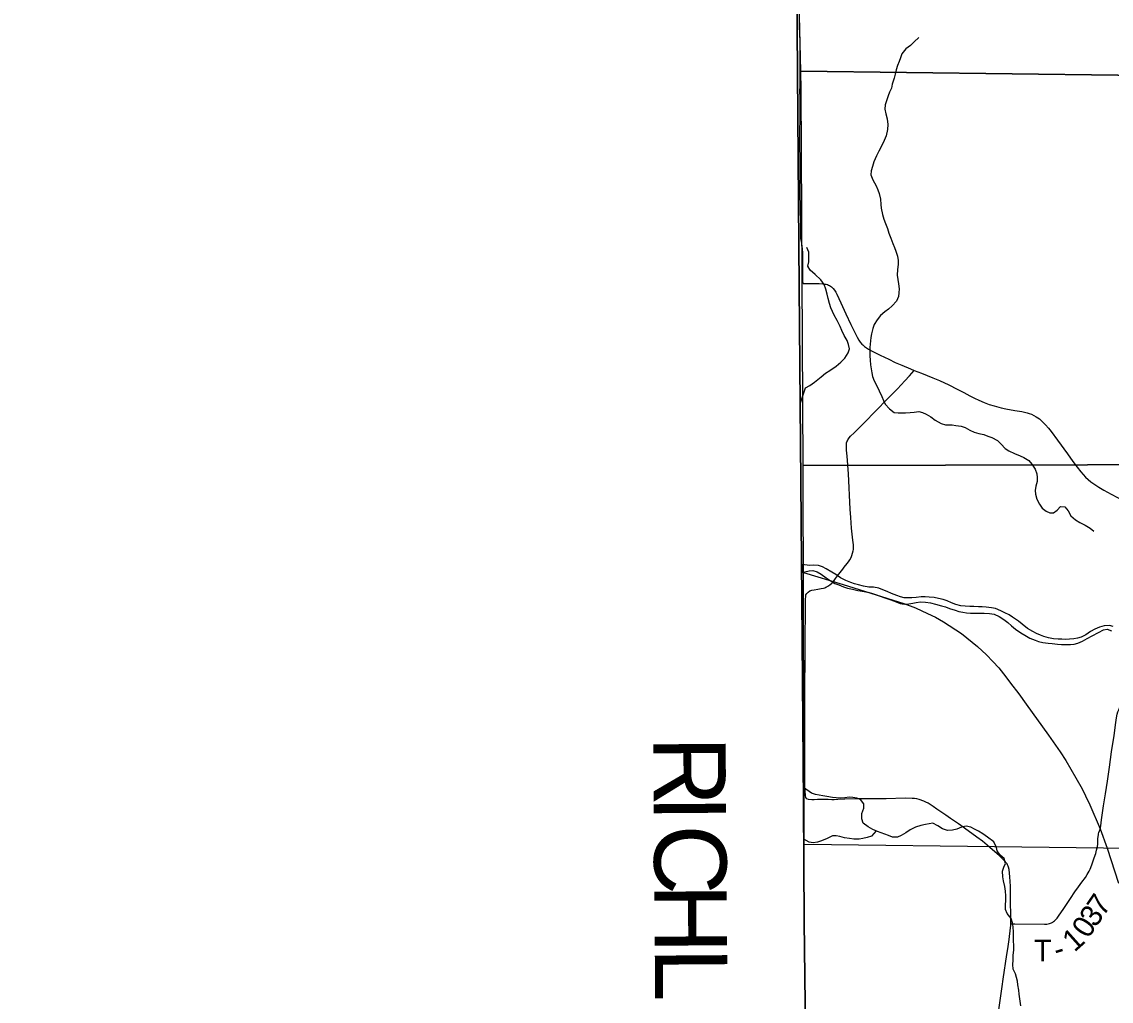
# Model space of a CAD drawing. Extents: x 1874609 to 2204689, y 815661 to 1281160.
# Drawn here: x 2002342 to 2017400, y 975217 to 988761 of the extents above; entities that cross this region are included whole.
import ezdxf

# ---------------------------------------------------------------- set-up
doc = ezdxf.new("R2010")
doc.units = 0
for name, color, linetype in [('GM_X_Adjacent_County', 7, 'Continuous'), ('GM_X_Adjacent_County_Text', 7, 'Continuous'), ('GM_X_County', 7, 'Continuous'), ('GM_X_County_Road', 7, 'Continuous'), ('GM_X_Major_River', 7, 'Continuous'), ('GM_X_Minor_River', 7, 'Continuous'), ('GM_X_Rail_Line', 7, 'Continuous'), ('GM_X_Section', 7, 'Continuous'), ('GM_X_State_Route', 7, 'Continuous'), ('GM_X_Township', 7, 'Continuous'), ('GM_X_Township_Road', 7, 'Continuous'), ('GM_X_Township_Road_Text', 7, 'Continuous')]:
    doc.layers.add(name, color=color, linetype=linetype)

msp = doc.modelspace()

# ---------------------------------------------------------------- linework, layer by layer
at = {"layer": 'GM_X_Adjacent_County'}
msp.add_lwpolyline([(2002342, 999536), (2002395, 993238), (2002881, 993241), (2003206, 993234), (2004504, 993233), (2007698, 993231), (2008414, 993238), (2008503, 993236), (2013055, 993227), (2013045, 990449), (2013083, 985682), (2013088, 985095), (2013122, 980772), (2013145, 977956), (2013158, 976319), (2013226, 970636), (2013231, 969069), (2013234, 968580), (2013273, 965999), (2013327, 961098), (2013338, 960130), (2013382, 956206), (2013389, 955699), (2013479, 950530)], dxfattribs=at)
at = {"layer": 'GM_X_County'}
msp.add_lwpolyline([(2013479, 950530), (2013389, 955699), (2013382, 956206), (2013338, 960130), (2013327, 961098), (2013273, 965999), (2013234, 968580), (2013231, 969069), (2013226, 970636), (2013158, 976319), (2013145, 977956), (2013122, 980772), (2013088, 985095), (2013083, 985682), (2013045, 990449), (2013055, 993227), (2008503, 993236), (2008414, 993238), (2007698, 993231), (2004504, 993233), (2003206, 993234), (2002881, 993241), (2002395, 993238), (2002342, 999536)], dxfattribs=at)
at = {"layer": 'GM_X_County_Road'}
for points in [[(2013711, 981218), (2013751, 981268), (2013770, 981295), (2013788, 981323), (2013804, 981352), (2013816, 981383), (2013826, 981415), (2013834, 981447), (2013836, 981464), (2013838, 981497), (2013836, 981530), (2013828, 981595), (2013810, 981759), (2013800, 981908), (2013793, 982020), (2013768, 982512), (2013750, 982755), (2013743, 982836), (2013739, 982888), (2013741, 982921), (2013743, 982937), (2013747, 982952), (2013753, 982967), (2013759, 982981), (2013768, 982995), (2013777, 983008), (2013798, 983032), (2013845, 983078), (2013962, 983194), (2014168, 983406), (2014283, 983523), (2014444, 983687), (2014546, 983794), (2014613, 983866), (2014645, 983904), (2014677, 983941)], [(2013475, 980951), (2013485, 980957), (2013499, 980966), (2013512, 980976), (2013537, 980997), (2013549, 981009), (2013560, 981022), (2013589, 981062), (2013619, 981100), (2013690, 981191), (2013711, 981218)], [(2013181, 980837), (2013193, 980857), (2013210, 980876), (2013233, 980891), (2013247, 980897), (2013262, 980901), (2013294, 980908), (2013343, 980914), (2013391, 980923), (2013424, 980930), (2013440, 980935), (2013455, 980941), (2013470, 980948), (2013475, 980951)], [(2013191, 978015), (2013178, 978036), (2013173, 978063), (2013168, 978127), (2013167, 978176), (2013165, 978225), (2013165, 978388), (2013165, 978486), (2013164, 978584), (2013165, 978649), (2013163, 978748), (2013164, 978780), (2013165, 978813), (2013163, 978960), (2013164, 979042), (2013164, 979123), (2013165, 979221), (2013165, 979352), (2013167, 979694), (2013168, 979825), (2013169, 979939), (2013169, 980119), (2013171, 980365), (2013173, 980479), (2013173, 980545), (2013173, 980626), (2013173, 980707), (2013174, 980772), (2013174, 980774)], [(2013174, 980774), (2013178, 980820), (2013181, 980837)], [(2016014, 976289), (2016014, 976316), (2016014, 976365), (2016013, 976451), (2016010, 976544), (2016007, 976593), (2016009, 976676), (2016009, 976806), (2016004, 976874), (2016001, 976939), (2015996, 976989), (2015988, 977038), (2015979, 977070), (2015974, 977087), (2015968, 977101), (2015960, 977116), (2015949, 977131), (2015931, 977154), (2015850, 977232), (2015758, 977312), (2015684, 977377), (2015621, 977429), (2015542, 977488), (2015422, 977575), (2015288, 977669), (2015180, 977744), (2015113, 977791), (2014992, 977874), (2014938, 977912), (2014896, 977938), (2014869, 977956), (2014839, 977972), (2014809, 977985), (2014747, 978005), (2014715, 978014), (2014682, 978020), (2014649, 978022), (2014551, 978023), (2014289, 978017), (2014207, 978016), (2014141, 978015), (2014076, 978015), (2013978, 978017), (2013929, 978016), (2013865, 978014), (2013718, 978010), (2013620, 978006), (2013571, 978004), (2013538, 978004), (2013489, 978005), (2013407, 978005), (2013342, 978005), (2013293, 978004), (2013260, 978003), (2013216, 978005), (2013191, 978015)], [(2015846, 975098), (2015864, 975228), (2015892, 975423), (2015906, 975520), (2015956, 975861), (2015969, 975941), (2015988, 976071), (2016010, 976234), (2016013, 976262), (2016014, 976289)]]:
    msp.add_lwpolyline(points, dxfattribs=at)
at = {"layer": 'GM_X_Major_River'}
msp.add_line((2013123, 981255), (2013123, 981147), dxfattribs=at)
for points in [[(2017429, 980400), (2017375, 980414), (2017303, 980408), (2017239, 980390), (2017173, 980360), (2017116, 980328), (2017050, 980284), (2016984, 980250), (2016934, 980236), (2016884, 980228), (2016824, 980222), (2016774, 980220), (2016719, 980222), (2016667, 980224), (2016601, 980230), (2016533, 980240), (2016471, 980260), (2016421, 980278), (2016367, 980302), (2016315, 980328), (2016245, 980372), (2016169, 980433), (2016118, 980473), (2016038, 980529), (2015988, 980561), (2015932, 980589), (2015874, 980617), (2015800, 980647), (2015746, 980657), (2015672, 980665), (2015618, 980669), (2015566, 980672), (2015499, 980674), (2015445, 980674), (2015381, 980678), (2015323, 980686), (2015251, 980704), (2015191, 980726), (2015131, 980752), (2015077, 980772), (2015012, 980788), (2014954, 980798), (2014882, 980806), (2014830, 980808), (2014774, 980808), (2014704, 980800), (2014642, 980796), (2014590, 980794), (2014539, 980796), (2014487, 980808), (2014437, 980826), (2014363, 980857), (2014303, 980883), (2014245, 980907), (2014187, 980927), (2014113, 980945), (2014049, 980943), (2013976, 980955), (2013906, 980975), (2013854, 980989), (2013800, 981007), (2013734, 981033), (2013658, 981073), (2013592, 981116), (2013540, 981150), (2013462, 981198), (2013410, 981226), (2013353, 981244), (2013285, 981248), (2013233, 981244), (2013123, 981255)], [(2013123, 981147), (2013227, 981170), (2013277, 981172), (2013337, 981154), (2013389, 981122), (2013458, 981073), (2013514, 981033), (2013580, 980995), (2013634, 980973), (2013700, 980947), (2013754, 980931), (2013826, 980913), (2013900, 980899), (2013956, 980889), (2014035, 980875), (2014089, 980859), (2014155, 980835), (2014255, 980802), (2014341, 980774), (2014407, 980748), (2014483, 980718), (2014537, 980708), (2014604, 980712), (2014656, 980720), (2014706, 980730), (2014766, 980738), (2014834, 980736), (2014904, 980726), (2014972, 980706), (2015056, 980684), (2015111, 980670), (2015167, 980650), (2015241, 980626), (2015295, 980607), (2015347, 980595), (2015399, 980587), (2015455, 980583), (2015646, 980583), (2015716, 980579), (2015784, 980571), (2015850, 980539), (2015918, 980497), (2015970, 980453), (2016022, 980407), (2016078, 980361), (2016150, 980312), (2016206, 980278), (2016275, 980238), (2016347, 980208), (2016397, 980190), (2016455, 980180), (2016527, 980170), (2016583, 980162), (2016657, 980156), (2016711, 980152), (2016765, 980150), (2016836, 980152), (2016890, 980156), (2016940, 980168), (2017004, 980198), (2017070, 980232), (2017138, 980270), (2017223, 980318), (2017293, 980354), (2017343, 980362), (2017405, 980338)]]:
    msp.add_lwpolyline(points, dxfattribs=at)
at = {"layer": 'GM_X_Minor_River'}
for points in [[(2014743, 988542), (2014678, 988483), (2014628, 988435), (2014562, 988385), (2014506, 988317), (2014486, 988263), (2014470, 988211), (2014448, 988157), (2014430, 988097), (2014413, 988036), (2014399, 987982), (2014373, 987900), (2014361, 987844), (2014335, 987788), (2014315, 987738), (2014293, 987670), (2014275, 987611), (2014271, 987553), (2014287, 987489), (2014302, 987419), (2014314, 987343), (2014310, 987271), (2014288, 987182), (2014262, 987120), (2014224, 987042), (2014186, 986970), (2014156, 986908), (2014121, 986825), (2014099, 986759), (2014081, 986701), (2014079, 986643), (2014105, 986577), (2014151, 986491), (2014173, 986438), (2014193, 986386), (2014211, 986308), (2014217, 986236), (2014221, 986186), (2014237, 986098), (2014259, 986031), (2014281, 985973), (2014307, 985901), (2014327, 985839), (2014353, 985769), (2014381, 985697), (2014403, 985638), (2014425, 985588), (2014445, 985518), (2014457, 985460), (2014457, 985406), (2014444, 985334), (2014442, 985257), (2014450, 985197), (2014460, 985139), (2014468, 985069), (2014466, 985011), (2014460, 984961), (2014432, 984900), (2014374, 984834), (2014324, 984788), (2014271, 984750), (2014211, 984700), (2014163, 984638), (2014125, 984574), (2014103, 984520), (2014085, 984446), (2014079, 984395), (2014062, 984255), (2014064, 984203), (2014064, 984143), (2014068, 984083), (2014072, 984016), (2014080, 983960), (2014090, 983906), (2014100, 983854), (2014122, 983798), (2014164, 983716), (2014192, 983660), (2014230, 983581), (2014252, 983525), (2014278, 983475), (2014336, 983407), (2014400, 983359), (2014454, 983355), (2014506, 983353), (2014556, 983353), (2014623, 983357), (2014675, 983363), (2014741, 983371), (2014791, 983360), (2014841, 983336), (2014909, 983298), (2014969, 983254), (2015049, 983208), (2015111, 983190), (2015202, 983186), (2015254, 983180), (2015328, 983168), (2015382, 983150), (2015444, 983116), (2015508, 983088)], [(2013105, 983490), (2013176, 983698), (2013234, 983732), (2013298, 983780), (2013389, 983850), (2013453, 983900), (2013511, 983937), (2013597, 983999), (2013663, 984053), (2013720, 984111), (2013764, 984185), (2013784, 984241), (2013770, 984299), (2013750, 984355), (2013710, 984424), (2013676, 984492), (2013652, 984546), (2013610, 984630), (2013570, 984704), (2013548, 984755), (2013524, 984807), (2013506, 984865), (2013488, 984935), (2013472, 984995), (2013456, 985063), (2013434, 985128), (2013388, 985192), (2013306, 985266), (2013240, 985328), (2013208, 985384), (2013220, 985440), (2013222, 985511), (2013220, 985575), (2013194, 985639)], [(2015508, 983088), (2015570, 983069), (2015640, 983053), (2015694, 983033), (2015749, 983013), (2015829, 982969), (2015877, 982919), (2015933, 982861), (2015985, 982827), (2016063, 982791), (2016143, 982758), (2016193, 982736), (2016261, 982696), (2016303, 982644), (2016351, 982576), (2016373, 982510), (2016379, 982458), (2016375, 982405), (2016359, 982341), (2016349, 982281), (2016353, 982231), (2016371, 982161), (2016409, 982089), (2016447, 982034), (2016501, 981992), (2016551, 981970), (2016601, 981972), (2016653, 982008), (2016701, 982058), (2016758, 982054), (2016806, 982000), (2016842, 981930), (2016906, 981876), (2016968, 981838), (2017040, 981798), (2017110, 981759), (2017160, 981719)], [(2013123, 981255), (2013123, 981147)], [(2013416, 978056), (2013364, 978068), (2013314, 978078), (2013258, 978096), (2013147, 978172)], [(2016150, 975154), (2016139, 975248), (2016127, 975314), (2016121, 975372), (2016111, 975444), (2016103, 975495), (2016089, 975545), (2016075, 975597), (2016047, 975659), (2016041, 975725), (2016043, 975783), (2016045, 975848), (2016053, 975930), (2016053, 975990), (2016051, 976052), (2016051, 976116), (2016049, 976174), (2016043, 976248), (2016038, 976299), (2016018, 976363), (2015964, 976431), (2015938, 976487), (2015938, 976551), (2015942, 976611), (2015942, 976676), (2015940, 976740), (2015932, 976802), (2015912, 976880), (2015902, 976938), (2015896, 977014), (2015918, 977073), (2015940, 977123), (2015920, 977191), (2015864, 977235), (2015822, 977295), (2015814, 977345), (2015778, 977421), (2015690, 977484), (2015624, 977532), (2015566, 977568), (2015512, 977598), (2015460, 977622), (2015394, 977636), (2015330, 977624), (2015267, 977598), (2015205, 977584), (2015139, 977576), (2015069, 977600), (2015005, 977644), (2014935, 977680), (2014835, 977662), (2014768, 977646), (2014696, 977624), (2014620, 977588), (2014560, 977548), (2014498, 977510), (2014444, 977488), (2014377, 977486), (2014323, 977508), (2014171, 977565), (2014103, 977593), (2014039, 977627), (2013973, 977681), (2013951, 977741), (2013955, 977815), (2013979, 977885), (2013981, 977948), (2013933, 978006), (2013883, 978024), (2013831, 978034), (2013779, 978038), (2013719, 978030), (2013662, 978026), (2013600, 978030), (2013546, 978034), (2013470, 978048), (2013416, 978056)], [(2014149, 977574), (2014085, 977498), (2014027, 977480), (2013968, 977466), (2013916, 977458), (2013842, 977458), (2013784, 977467), (2013714, 977477), (2013650, 977493), (2013600, 977505), (2013548, 977505), (2013475, 977467), (2013397, 977433), (2013339, 977417), (2013281, 977407), (2013223, 977415), (2013153, 977457)]]:
    msp.add_lwpolyline(points, dxfattribs=at)
at = {"layer": 'GM_X_Rail_Line'}
msp.add_lwpolyline([(2013149, 981147), (2013696, 980978), (2014534, 980716), (2014693, 980657), (2014860, 980581), (2014971, 980527), (2015084, 980464), (2015331, 980303), (2015551, 980124), (2015678, 980007), (2015766, 979914), (2015845, 979826), (2015944, 979705), (2016010, 979617), (2016121, 979467), (2016225, 979324), (2016534, 978897), (2016600, 978802), (2016694, 978668), (2016773, 978544), (2016913, 978307), (2016998, 978152), (2017045, 978057), (2017106, 977935), (2017248, 977600), (2017342, 977335), (2017499, 976851)], dxfattribs=at)
at = {"layer": 'GM_X_Section'}
for points in [[(2013063, 993254), (2019028, 993166), (2018951, 988004), (2013110, 988078), (2013047, 990766)], [(2018951, 988004), (2019042, 982641), (2013142, 982627), (2013116, 987822), (2013110, 988078)], [(2013143, 982493), (2013142, 982627), (2019042, 982641), (2019175, 977309), (2013155, 977383)]]:
    msp.add_lwpolyline(points, close=True, dxfattribs=at)
at = {"layer": 'GM_X_State_Route'}
msp.add_lwpolyline([(2013140, 985144), (2013201, 985144), (2013365, 985140), (2013414, 985139), (2013446, 985135), (2013462, 985131), (2013477, 985127), (2013492, 985121), (2013506, 985114), (2013520, 985105), (2013533, 985096), (2013544, 985085), (2013556, 985073), (2013576, 985048), (2013594, 985021), (2013609, 984993), (2013636, 984933), (2013664, 984874), (2013732, 984725), (2013801, 984576), (2013851, 984472), (2013890, 984400), (2013914, 984357), (2013932, 984329), (2013954, 984304), (2013965, 984292), (2013991, 984270), (2014018, 984251), (2014046, 984234), (2014104, 984202), (2014207, 984152), (2014325, 984094), (2014414, 984052), (2014504, 984013), (2014626, 983963), (2014677, 983941), (2014777, 983900), (2014935, 983837), (2015026, 983800), (2015157, 983740), (2015270, 983683), (2015365, 983634), (2015445, 983589), (2015511, 983557), (2015572, 983528), (2015644, 983497), (2015711, 983470), (2015781, 983449), (2015881, 983421), (2015945, 983407), (2016066, 983386), (2016165, 983370), (2016240, 983352), (2016267, 983343), (2016298, 983333), (2016330, 983318), (2016362, 983300), (2016407, 983269), (2016449, 983230), (2016492, 983188), (2016534, 983140), (2016572, 983094), (2016660, 982977), (2016794, 982789), (2016872, 982683), (2016930, 982604), (2016980, 982539), (2017011, 982501), (2017046, 982465), (2017082, 982432), (2017120, 982400), (2017174, 982362), (2017229, 982325), (2017299, 982284), (2017400, 982228), (2017575, 982137)], dxfattribs=at)
at = {"layer": 'GM_X_Township'}
msp.add_lwpolyline([(2013226, 970636), (2013158, 976319), (2013145, 977956), (2013122, 980772), (2013088, 985095), (2013083, 985682), (2013045, 990449), (2013055, 993227), (2019008, 993199), (2023012, 993180), (2027008, 993161), (2032163, 993089), (2034988, 993049), (2040325, 993088), (2045626, 993121), (2045602, 990454), (2045625, 987740), (2045624, 987592), (2045643, 985092), (2045777, 977423), (2045852, 971713)], dxfattribs=at)
at = {"layer": 'GM_X_Township_Road'}
for points in [[(2013096, 987166), (2013096, 987185), (2013098, 987283), (2013100, 987381), (2013100, 987511), (2013099, 987626), (2013099, 987708), (2013098, 987806), (2013100, 987872), (2013101, 987904), (2013101, 987953), (2013100, 988100), (2013100, 988133), (2013101, 988198), (2013100, 988264), (2013101, 988296), (2013101, 988325), (2013100, 988355), (2013100, 988380), (2013100, 988421), (2013100, 988448), (2013100, 988486), (2013097, 988600), (2013093, 988698), (2013091, 988764)], [(2013116, 985742), (2013112, 985764), (2013109, 985810), (2013108, 985875), (2013108, 985974), (2013102, 986399), (2013101, 986546), (2013101, 986628), (2013100, 986726), (2013101, 986808), (2013099, 986907), (2013098, 987005), (2013096, 987087), (2013096, 987166)], [(2013140, 985144), (2013139, 985173), (2013139, 985271), (2013139, 985435), (2013137, 985566), (2013133, 985615), (2013123, 985696), (2013118, 985728), (2013116, 985742)], [(2017376, 978453), (2017406, 978667), (2017440, 978894), (2017464, 979073), (2017473, 979138), (2017482, 979186), (2017492, 979218), (2017504, 979248), (2017512, 979262), (2017530, 979290), (2017560, 979329), (2017643, 979430), (2017749, 979558)], [(2016014, 976289), (2016069, 976288), (2016477, 976281), (2016495, 976282), (2016511, 976284), (2016529, 976286), (2016545, 976290), (2016562, 976296), (2016577, 976303), (2016591, 976311), (2016604, 976321), (2016617, 976331), (2016629, 976342), (2016651, 976367), (2016670, 976393), (2016745, 976500), (2016799, 976581), (2016836, 976636), (2016899, 976731), (2016947, 976798), (2016995, 976864), (2017043, 976930), (2017070, 976971), (2017094, 977014), (2017108, 977044), (2017132, 977105), (2017165, 977198), (2017186, 977260), (2017199, 977307), (2017209, 977355), (2017213, 977388), (2017216, 977453), (2017217, 977469), (2017223, 977518), (2017226, 977534), (2017230, 977550), (2017241, 977581), (2017246, 977596), (2017256, 977644), (2017268, 977725), (2017295, 977920), (2017319, 978083), (2017347, 978261), (2017372, 978423), (2017376, 978453)]]:
    msp.add_lwpolyline(points, dxfattribs=at)

# ---------------------------------------------------------------- texts
at = {"layer": 'GM_X_Adjacent_County_Text'}
for s, rotation, p in [('R', 270.4159, (2011070, 978879)), ('I', 270.4136, (2011076, 978065)), ('C', 270.4159, (2011079, 977655)), ('H', 270.4155, (2011085, 976841)), ('L', 270.4156, (2011091, 975957))]:
    msp.add_text(s, height=1000, rotation=rotation, dxfattribs=at).set_placement(p)
at = {"layer": 'GM_X_Township_Road_Text'}
for s, rotation, p in [('7', 55.4687, (2017290, 976378)), ('3', 55.4381, (2017185, 976225)), ('0', 56.3221, (2017083, 976072)), ('1', 41.7033, (2016891, 975887)), ('T', 0.1929, (2016332, 975767)), ('-', 17.1992, (2016652, 975782))]:
    msp.add_text(s, height=300, rotation=rotation, dxfattribs=at).set_placement(p)

doc.saveas('drawing.dxf')
